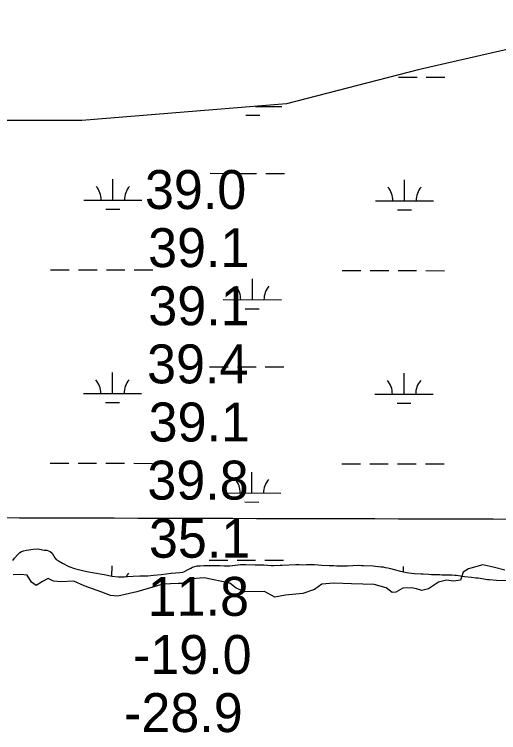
# Model space of a CAD drawing. Extents: x 3180038 to 3217926, y 922069 to 947485.
# Drawn here: x 3184434 to 3185268, y 933212 to 934447 of the extents above; entities that cross this region are included whole.
import ezdxf

# ---------------------------------------------------------------- set-up
doc = ezdxf.new("R2010")
doc.units = 0
for name, color, linetype in [('V-GRID-MAJR', 7, 'Continuous'), ('V-RIVR-EDGE', 7, 'Continuous'), ('V-RIVR-RANG', 7, 'Continuous'), ('V-SITE-VEGE', 7, 'Continuous'), ('V-WETL-SWMP', 7, 'Continuous')]:
    doc.layers.add(name, color=color, linetype=linetype)

msp = doc.modelspace()

# ---------------------------------------------------------------- linework, layer by layer
at = {"layer": 'V-GRID-MAJR'}
msp.add_spline([(3184280, 933581.8), (3186889.6, 933574.8), (3192108.7, 933561.5), (3197327.7, 933549), (3202546.8, 933537.2), (3207765.9, 933526.2), (3212985, 933516), (3215594.6, 933511.2)], degree=3, dxfattribs=at)
at = {"layer": 'V-RIVR-EDGE'}
msp.add_lwpolyline([(3185278.6, 933490.9), (3185260.5, 933495.6), (3185240.3, 933500.4), (3185215.9, 933493.2), (3185207, 933487.5), (3185202.3, 933474), (3185189.9, 933472), (3185178, 933474.1), (3185164.5, 933470.5), (3185147.3, 933459.1), (3185135.4, 933456), (3185126.6, 933459.2), (3185117.8, 933460.7), (3185102.7, 933460.3), (3185090.8, 933453), (3185084.5, 933452.5), (3185074.2, 933460.8), (3185053.5, 933466.6), (3185014.6, 933467.7), (3184984, 933468.8), (3184963.7, 933466.8), (3184950.8, 933458), (3184931, 933450.8), (3184900.9, 933447.8), (3184882.8, 933444.7), (3184864.7, 933454.6), (3184830.9, 933453.7), (3184815.9, 933459.9), (3184805, 933468.8), (3184761, 933477.7), (3184733, 933475.7), (3184729.3, 933467.9), (3184716.4, 933468), (3184689.9, 933467), (3184645.3, 933453.6), (3184612.1, 933446.4), (3184599.6, 933447.5), (3184585.1, 933453.2), (3184554.5, 933464.2), (3184536.4, 933472), (3184514.1, 933471), (3184501.7, 933472.1), (3184492.3, 933476.8), (3184483, 933471.6), (3184471.6, 933464.9), (3184463.8, 933470.7), (3184456.1, 933482.6), (3184445.7, 933483.7), (3184432.2, 933483.2)], dxfattribs=at)
at = {"layer": 'V-SITE-VEGE'}
for p, q in [((3184434.3, 933511.5), (3184440.2, 933518)), ((3184440.2, 933518), (3184443.7, 933521.2)), ((3184443.7, 933521.2), (3184446.3, 933523.2)), ((3184446.3, 933523.2), (3184450.1, 933524.4)), ((3184450.1, 933524.4), (3184455.4, 933525.7)), ((3184455.4, 933525.7), (3184466.6, 933527.4)), ((3184466.6, 933527.4), (3184474.5, 933527.9)), ((3184474.5, 933527.9), (3184477.5, 933527.2)), ((3184477.5, 933527.2), (3184485.7, 933525.7)), ((3184485.7, 933525.7), (3184490.1, 933525.3)), ((3184490.1, 933525.3), (3184493.1, 933524.4)), ((3184493.1, 933524.4), (3184495.9, 933523)), ((3184495.9, 933523), (3184499.3, 933520.1)), ((3184499.3, 933520.1), (3184501.8, 933516.3)), ((3184431.9, 933507.9), (3184434.3, 933511.5)), ((3184501.8, 933516.3), (3184503.8, 933512.5)), ((3184503.8, 933512.5), (3184506.4, 933509.6)), ((3184506.4, 933509.6), (3184510.1, 933507)), ((3184510.1, 933507), (3184517.1, 933502.9)), ((3184517.1, 933502.9), (3184528.1, 933497.3)), ((3184528.1, 933497.3), (3184537.9, 933493.8)), ((3184537.9, 933493.8), (3184551.3, 933490.4)), ((3184731, 933491), (3184737.9, 933494.6)), ((3184737.9, 933494.6), (3184741.1, 933496.1)), ((3184741.1, 933496.1), (3184748.8, 933498.4)), ((3184748.8, 933498.4), (3184754.2, 933498.8)), ((3184754.2, 933498.8), (3184760.4, 933499.1)), ((3184760.4, 933499.1), (3184773.7, 933499.1)), ((3184773.7, 933499.1), (3184780.5, 933499.3)), ((3184780.5, 933499.3), (3184787.7, 933499.4)), ((3184787.7, 933499.4), (3184795.9, 933498.5)), ((3184795.9, 933498.5), (3184805.2, 933498.4)), ((3184805.2, 933498.4), (3184823.5, 933500.7)), ((3184823.5, 933500.7), (3184832.9, 933500.8)), ((3184832.9, 933500.8), (3184848.6, 933500.2)), ((3184848.6, 933500.2), (3184863.4, 933500.1)), ((3184863.4, 933500.1), (3184876.2, 933499.1)), ((3184876.2, 933499.1), (3184880.9, 933499.2)), ((3184880.9, 933499.2), (3184891.9, 933499.7)), ((3184891.9, 933499.7), (3184895.3, 933499.5)), ((3184895.3, 933499.5), (3184919, 933501)), ((3184919, 933501), (3184924.5, 933500.9)), ((3184924.5, 933500.9), (3184929.9, 933500.4)), ((3184929.9, 933500.4), (3184937.3, 933500.8)), ((3184937.3, 933500.8), (3184950.6, 933501)), ((3184950.6, 933501), (3184963.6, 933499.8)), ((3184963.6, 933499.8), (3184976.2, 933499.1)), ((3184976.2, 933499.1), (3184983.3, 933499)), ((3184983.3, 933499), (3184989.5, 933498.7)), ((3184989.5, 933498.7), (3184996.9, 933498.6)), ((3184996.9, 933498.6), (3185001.1, 933498.8)), ((3185001.1, 933498.8), (3185007.5, 933498.5)), ((3185007.5, 933498.5), (3185025.8, 933499.7)), ((3185025.8, 933499.7), (3185031.6, 933499.2)), ((3185031.6, 933499.2), (3185035.3, 933499.2)), ((3185035.3, 933499.2), (3185051.7, 933498.4)), ((3185051.7, 933498.4), (3185056.1, 933498.1)), ((3185056.1, 933498.1), (3185065.9, 933496.6)), ((3185065.9, 933496.6), (3185069, 933496.7)), ((3185069, 933496.7), (3185072.2, 933495.9)), ((3185072.2, 933495.9), (3185077.2, 933495.2)), ((3185077.2, 933495.2), (3185081.6, 933494.2)), ((3185081.6, 933494.2), (3185088, 933492.1)), ((3184551.3, 933490.4), (3184559.1, 933488.7)), ((3184559.1, 933488.7), (3184585.4, 933484)), ((3184585.4, 933484), (3184588.6, 933483.7)), ((3184588.6, 933483.7), (3184594.6, 933482.2)), ((3184594.6, 933482.2), (3184602.2, 933480.9)), ((3184602.2, 933480.9), (3184613, 933479.8)), ((3184629.1, 933480.2), (3184638.5, 933480.5)), ((3184638.5, 933480.5), (3184650.4, 933481.4)), ((3184650.4, 933481.4), (3184655.2, 933481.5)), ((3184655.2, 933481.5), (3184663.8, 933481.2)), ((3184663.8, 933481.2), (3184673.5, 933482.5)), ((3184673.5, 933482.5), (3184686.7, 933483.7)), ((3184686.7, 933483.7), (3184704.2, 933485.9)), ((3184704.2, 933485.9), (3184718.9, 933487)), ((3184718.9, 933487), (3184724.3, 933487.9)), ((3184724.3, 933487.9), (3184727.2, 933488.7)), ((3184727.2, 933488.7), (3184731, 933491)), ((3185088, 933492.1), (3185096.6, 933489.8)), ((3185096.6, 933489.8), (3185109.2, 933487.2)), ((3185109.2, 933487.2), (3185117.6, 933485.9)), ((3185117.6, 933485.9), (3185123.2, 933485.3)), ((3185123.2, 933485.3), (3185134.7, 933484.9)), ((3185134.7, 933484.9), (3185138.1, 933484.5)), ((3185138.1, 933484.5), (3185147.5, 933484.2)), ((3185147.5, 933484.2), (3185152.5, 933483.7)), ((3185152.5, 933483.7), (3185155.9, 933484)), ((3185155.9, 933484), (3185162.2, 933483.8)), ((3185162.2, 933483.8), (3185166.4, 933483.7)), ((3185166.4, 933483.7), (3185169.8, 933483.3)), ((3185169.8, 933483.3), (3185180.8, 933483.3)), ((3185180.8, 933483.3), (3185187.2, 933482.9)), ((3185187.2, 933482.9), (3185192.1, 933482.4)), ((3185192.1, 933482.4), (3185195.3, 933482.2)), ((3185195.3, 933482.2), (3185208.9, 933480.4)), ((3184613, 933479.8), (3184618.6, 933479.7)), ((3184618.6, 933479.7), (3184623.5, 933479.7)), ((3184623.5, 933479.7), (3184629.1, 933480.2)), ((3185208.9, 933480.4), (3185220.9, 933479.2)), ((3185220.9, 933479.2), (3185228.7, 933478.1)), ((3185228.7, 933478.1), (3185232.4, 933477.7)), ((3185232.4, 933477.7), (3185248.4, 933475.1)), ((3185248.4, 933475.1), (3185252, 933474.9)), ((3185252, 933474.9), (3185264.2, 933473.9)), ((3185264.2, 933473.9), (3185285.5, 933473.2))]:
    msp.add_line(p, q, dxfattribs=at)
at = {"layer": 'V-WETL-SWMP'}
for p, q in [((3185547.1, 934447.4), (3185129.5, 934351.9)), ((3185129.5, 934351.9), (3184902.6, 934293.5)), ((3185095.3, 934339.3), (3185127.3, 934339.2)), ((3185143.3, 934339.2), (3185175.3, 934339.1)), ((3184902.6, 934293.5), (3184550.3, 934264.8)), ((3184849.2, 934289.1), (3184894.6, 934289)), ((3184832.6, 934273.7), (3184856.6, 934273.7)), ((3184550.3, 934264.8), (3184281.9, 934264.9)), ((3184771, 934173.9), (3184803, 934173.8)), ((3184819, 934173.7), (3184851, 934173.7)), ((3184867, 934173.6), (3184899, 934173.6)), ((3184603.8, 934127.8), (3184603.9, 934163.8)), ((3185105.7, 934126.7), (3185105.8, 934162.7)), ((3184553.8, 934127.9), (3184653.8, 934127.7)), ((3185055.7, 934126.8), (3185155.7, 934126.6)), ((3184591.8, 934112.4), (3184615.8, 934112.3)), ((3185093.7, 934111.3), (3185117.7, 934111.2)), ((3184496.7, 934008), (3184528.7, 934007.9)), ((3184544.7, 934007.9), (3184576.7, 934007.8)), ((3184592.7, 934007.8), (3184624.7, 934007.7)), ((3184640.7, 934007.6), (3184672.7, 934007.6)), ((3184998.6, 934006.8), (3185030.6, 934006.8)), ((3185046.6, 934006.7), (3185078.6, 934006.7)), ((3185094.6, 934006.6), (3185126.6, 934006.6)), ((3185142.6, 934006.5), (3185174.6, 934006.4)), ((3184843.9, 933956.4), (3184844, 933992.4)), ((3184793.9, 933956.6), (3184893.9, 933956.3)), ((3184831.8, 933941), (3184855.8, 933941)), ((3184770.2, 933841.2), (3184802.2, 933841.1)), ((3184818.2, 933841.1), (3184850.2, 933841)), ((3184866.2, 933841), (3184898.2, 933840.9)), ((3184603, 933795.1), (3184603.1, 933831.1)), ((3185104.9, 933794), (3185105, 933830)), ((3184553, 933795.2), (3184653, 933795)), ((3185054.9, 933794.1), (3185154.9, 933793.9)), ((3184591, 933779.7), (3184615, 933779.7)), ((3185092.9, 933778.6), (3185116.9, 933778.5)), ((3184495.9, 933675.3), (3184527.9, 933675.2)), ((3184543.9, 933675.2), (3184575.9, 933675.1)), ((3184591.9, 933675.1), (3184623.9, 933675)), ((3184639.9, 933675), (3184671.9, 933674.9)), ((3184997.8, 933674.2), (3185029.8, 933674.1)), ((3185045.8, 933674.1), (3185077.8, 933674)), ((3185093.8, 933674), (3185125.8, 933673.9)), ((3185141.8, 933673.8), (3185173.8, 933673.8)), ((3184843.1, 933623.8), (3184843.2, 933659.8)), ((3184793.1, 933623.9), (3184893.1, 933623.7)), ((3184831.1, 933608.4), (3184855.1, 933608.3)), ((3184434.3, 933511.5), (3184440.2, 933517.9)), ((3184440.2, 933517.9), (3184443.7, 933521.2)), ((3184443.7, 933521.2), (3184446.3, 933523.2)), ((3184446.3, 933523.2), (3184450.1, 933524.4)), ((3184450.1, 933524.4), (3184455.4, 933525.7)), ((3184455.4, 933525.7), (3184466.6, 933527.4)), ((3184466.6, 933527.4), (3184474.5, 933527.9)), ((3184474.5, 933527.9), (3184477.5, 933527.2)), ((3184477.5, 933527.2), (3184485.7, 933525.7)), ((3184485.7, 933525.7), (3184490.1, 933525.3)), ((3184490.1, 933525.3), (3184493.1, 933524.4)), ((3184493.1, 933524.4), (3184495.9, 933523)), ((3184495.9, 933523), (3184499.3, 933520.1)), ((3184499.3, 933520.1), (3184501.8, 933516.3)), ((3184501.8, 933516.3), (3184503.8, 933512.5)), ((3184503.8, 933512.5), (3184506.4, 933509.6)), ((3184506.4, 933509.6), (3184510, 933507)), ((3184510, 933507), (3184517.1, 933502.9)), ((3184769.5, 933508.5), (3184801.5, 933508.4)), ((3184817.5, 933508.4), (3184849.5, 933508.3)), ((3184865.5, 933508.3), (3184897.5, 933508.2)), ((3184517.1, 933502.9), (3184528.1, 933497.3)), ((3184528.1, 933497.3), (3184537.9, 933493.8)), ((3184537.9, 933493.8), (3184551.3, 933490.4)), ((3184602.3, 933480.8), (3184602.4, 933498.5)), ((3184731, 933491), (3184737.9, 933494.6)), ((3184737.9, 933494.6), (3184741.1, 933496.1)), ((3184741.1, 933496.1), (3184748.8, 933498.4)), ((3184748.8, 933498.4), (3184754.2, 933498.8)), ((3184754.2, 933498.8), (3184760.4, 933499.1)), ((3184760.4, 933499.1), (3184773.7, 933499.1)), ((3184773.7, 933499.1), (3184780.5, 933499.3)), ((3184780.5, 933499.3), (3184787.7, 933499.4)), ((3184787.7, 933499.4), (3184795.9, 933498.5)), ((3184795.9, 933498.5), (3184805.2, 933498.4)), ((3184805.2, 933498.4), (3184823.5, 933500.7)), ((3184823.5, 933500.7), (3184832.9, 933500.8)), ((3184832.9, 933500.8), (3184848.6, 933500.2)), ((3184848.6, 933500.2), (3184863.4, 933500.1)), ((3184863.4, 933500.1), (3184876.1, 933499.1)), ((3184876.1, 933499.1), (3184880.9, 933499.2)), ((3184880.9, 933499.2), (3184891.9, 933499.7)), ((3184891.9, 933499.7), (3184895.3, 933499.5)), ((3184895.3, 933499.5), (3184919, 933501)), ((3184919, 933501), (3184924.5, 933500.9)), ((3184924.5, 933500.9), (3184929.9, 933500.3)), ((3184929.9, 933500.3), (3184937.3, 933500.8)), ((3184937.3, 933500.8), (3184950.6, 933501)), ((3184950.6, 933501), (3184963.6, 933499.8)), ((3184963.6, 933499.8), (3184976.2, 933499.1)), ((3184976.2, 933499.1), (3184983.3, 933499)), ((3184983.3, 933499), (3184989.5, 933498.7)), ((3184989.5, 933498.7), (3184996.9, 933498.6)), ((3184996.9, 933498.6), (3185001.1, 933498.8)), ((3185001.1, 933498.8), (3185007.4, 933498.5)), ((3185007.4, 933498.5), (3185025.8, 933499.7)), ((3185025.8, 933499.7), (3185031.5, 933499.2)), ((3185031.5, 933499.2), (3185035.3, 933499.2)), ((3185035.3, 933499.2), (3185051.7, 933498.4)), ((3185051.7, 933498.4), (3185056.1, 933498.1)), ((3185056.1, 933498.1), (3185065.8, 933496.6)), ((3185065.8, 933496.6), (3185069, 933496.6)), ((3185069, 933496.6), (3185072.2, 933495.9)), ((3185072.2, 933495.9), (3185077.2, 933495.2)), ((3185077.2, 933495.2), (3185081.6, 933494.2)), ((3185081.6, 933494.2), (3185088, 933492.1)), ((3185104.3, 933488.2), (3185104.3, 933497.3)), ((3184551.3, 933490.4), (3184559.1, 933488.7)), ((3184559.1, 933488.7), (3184585.4, 933484)), ((3184585.4, 933484), (3184588.6, 933483.7)), ((3184588.6, 933483.7), (3184594.6, 933482.2)), ((3184594.6, 933482.2), (3184602.2, 933480.9)), ((3184602.2, 933480.9), (3184613, 933479.8)), ((3184629.1, 933480.2), (3184638.5, 933480.5)), ((3184638.5, 933480.5), (3184650.4, 933481.4)), ((3184650.4, 933481.4), (3184655.2, 933481.5)), ((3184655.2, 933481.5), (3184663.8, 933481.2)), ((3184663.8, 933481.2), (3184673.5, 933482.5)), ((3184673.5, 933482.5), (3184686.7, 933483.7)), ((3184686.7, 933483.7), (3184704.2, 933485.9)), ((3184704.2, 933485.9), (3184718.9, 933487)), ((3184718.9, 933487), (3184724.3, 933487.9)), ((3184724.3, 933487.9), (3184727.2, 933488.7)), ((3184727.2, 933488.7), (3184731, 933491)), ((3185088, 933492.1), (3185096.6, 933489.8)), ((3185096.6, 933489.8), (3185109.2, 933487.2)), ((3185109.2, 933487.2), (3185117.6, 933485.9)), ((3185117.6, 933485.9), (3185123.2, 933485.3)), ((3185123.2, 933485.3), (3185134.7, 933484.9)), ((3185134.7, 933484.9), (3185138.1, 933484.5)), ((3185138.1, 933484.5), (3185147.5, 933484.2)), ((3185147.5, 933484.2), (3185152.5, 933483.7)), ((3185152.5, 933483.7), (3185155.9, 933483.9)), ((3185155.9, 933483.9), (3185162.2, 933483.8)), ((3185162.2, 933483.8), (3185166.4, 933483.7)), ((3185166.4, 933483.7), (3185169.8, 933483.3)), ((3185169.8, 933483.3), (3185180.8, 933483.3)), ((3185180.8, 933483.3), (3185187.2, 933482.9)), ((3185187.2, 933482.9), (3185192.1, 933482.4)), ((3185192.1, 933482.4), (3185195.3, 933482.2)), ((3185195.3, 933482.2), (3185208.9, 933480.4)), ((3184613, 933479.8), (3184618.6, 933479.7)), ((3184618.6, 933479.7), (3184623.5, 933479.7)), ((3184623.5, 933479.7), (3184629.1, 933480.2)), ((3185208.9, 933480.4), (3185220.9, 933479.2)), ((3185220.9, 933479.2), (3185228.7, 933478.1)), ((3185228.7, 933478.1), (3185232.4, 933477.7)), ((3185232.4, 933477.7), (3185248.4, 933475.1)), ((3185248.4, 933475.1), (3185252, 933474.9)), ((3185252, 933474.9), (3185264.2, 933473.9)), ((3185264.2, 933473.9), (3185285.5, 933473.2))]:
    msp.add_line(p, q, dxfattribs=at)
for centre, start, end in [((3184899.9, 934289.5), 178.5542, 180.6427), ((3184548.5, 934128.4), 359.099, 40.6427), ((3184659, 934128.2), 139.099, 180.6427), ((3185050.5, 934127.3), 359.099, 40.6427), ((3185160.9, 934127), 139.099, 180.6427), ((3184788.6, 933957), 359.099, 40.6427), ((3184899.1, 933956.8), 139.099, 180.6427), ((3184547.8, 933795.7), 359.099, 40.6427), ((3184658.3, 933795.5), 139.099, 180.6427), ((3185049.7, 933794.6), 359.099, 40.6427), ((3185160.2, 933794.3), 139.099, 180.6427), ((3184787.9, 933624.4), 359.099, 40.6427), ((3184898.4, 933624.1), 139.099, 180.6427), ((3184657.5, 933462.8), 139.099, 150.8317)]:
    msp.add_arc(centre, 35.2, start, end, dxfattribs=at)

# ---------------------------------------------------------------- texts
at = {"layer": 'V-RIVR-RANG'}
for s, p in [('39.0', (3184659, 934112.5)), ('39.1', (3184664.5, 934012.5)), ('39.1', (3184664.8, 933912.5)), ('39.4', (3184662.7, 933812.5)), ('39.1', (3184665.3, 933712.5)), ('39.8', (3184663.2, 933612.5)), ('35.1', (3184665.9, 933512.5)), ('11.8', (3184663.8, 933412.5))]:
    msp.add_text(s, height=67, rotation=0.0083, dxfattribs=at).set_placement(p)
for s, p in [('-19.0', (3184638.4, 933312.5)), ('-28.9', (3184623.1, 933212.5))]:
    msp.add_text(s, height=67, dxfattribs=at).set_placement(p)

doc.saveas('drawing.dxf')
